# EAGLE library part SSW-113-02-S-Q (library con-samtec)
THROUGH-HOLE .025" SQ POST SOCKET Source: Samtec SSW.pdf
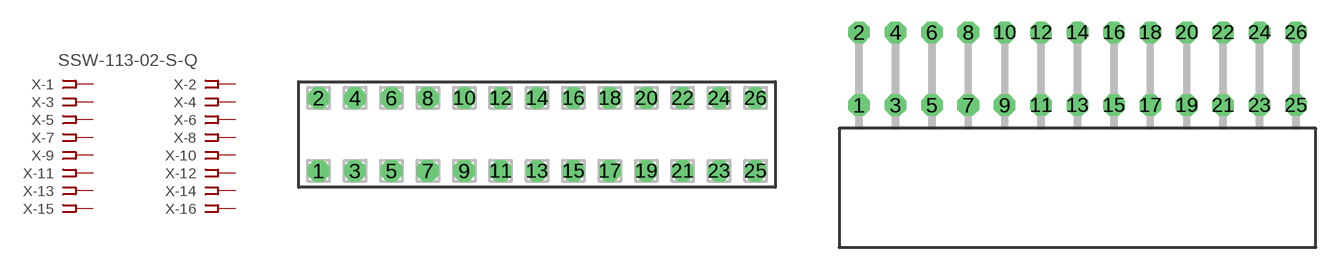
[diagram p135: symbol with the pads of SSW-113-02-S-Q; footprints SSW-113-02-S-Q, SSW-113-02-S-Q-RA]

Designator prefix X; gates -1=FPINV -2=FPIN -3=FPIN -4=FPIN -5=FPIN -6=FPIN -7=FPIN -8=FPIN -9=FPIN -10=FPIN -11=FPIN -12=FPIN -13=FPIN -14=FPIN -15=FPIN -16=FPIN -17=FPIN -18=FPIN -19=FPIN -20=FPIN -21=FPIN -22=FPIN -23=FPIN -24=FPIN -25=FPIN -26=FPIN

## SSW-113-02-S-Q (MPN: SSW-113-02-S-Q; OC_FARNELL: unknown; OC_NEWARK: 82P6267)  [SSW-113-02-S-Q]
1  -1:1  pas
2  -2:1  pas
3  -3:1  pas
4  -4:1  pas
5  -5:1  pas
6  -6:1  pas
7  -7:1  pas
8  -8:1  pas
9  -9:1  pas
10  -10:1  pas
11  -11:1  pas
12  -12:1  pas
13  -13:1  pas
14  -14:1  pas
15  -15:1  pas
16  -16:1  pas
17  -17:1  pas
18  -18:1  pas
19  -19:1  pas
20  -20:1  pas
21  -21:1  pas
22  -22:1  pas
23  -23:1  pas
24  -24:1  pas
25  -25:1  pas
26  -26:1  pas

## SSW-113-02-S-QRA (MPN: SSW-113-02-S-Q-RA; OC_FARNELL: unknown; OC_NEWARK: 82P6268)  [SSW-113-02-S-Q-RA]
Pads as for SSW-113-02-S-Q

## Footprint SSW-113-02-S-Q (pad centres in mm)
THROUGH-HOLE .025" SQ POST SOCKET Source: Samtec SSW.pdf
drill 1 pad 1.5 octagon: 1 -15.24,-2.54; 2 -15.24,2.54; 3 -12.7,-2.54; 4 -12.7,2.54; 5 -10.16,-2.54; 6 -10.16,2.54; 7 -7.62,-2.54; 8 -7.62,2.54; 9 -5.08,-2.54; 10 -5.08,2.54; 11 -2.54,-2.54; 12 -2.54,2.54; 13 0,-2.54; 14 0,2.54; 15 2.54,-2.54; 16 2.54,2.54; 17 5.08,-2.54; 18 5.08,2.54; 19 7.62,-2.54; 20 7.62,2.54; 21 10.16,-2.54; 22 10.16,2.54; 23 12.7,-2.54; 24 12.7,2.54; 25 15.24,-2.54; 26 15.24,2.54

## Footprint SSW-113-02-S-Q-RA (pad centres in mm)
THROUGH-HOLE .025" SQ POST SOCKET Source: Samtec SSW.pdf
drill 1 pad 1.5 octagon: 1 -15.24,1.524; 2 -15.24,6.604; 3 -12.7,1.524; 4 -12.7,6.604; 5 -10.16,1.524; 6 -10.16,6.604; 7 -7.62,1.524; 8 -7.62,6.604; 9 -5.08,1.524; 10 -5.08,6.604; 11 -2.54,1.524; 12 -2.54,6.604; 13 0,1.524; 14 0,6.604; 15 2.54,1.524; 16 2.54,6.604; 17 5.08,1.524; 18 5.08,6.604; 19 7.62,1.524; 20 7.62,6.604; 21 10.16,1.524; 22 10.16,6.604; 23 12.7,1.524; 24 12.7,6.604; 25 15.24,1.524; 26 15.24,6.604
